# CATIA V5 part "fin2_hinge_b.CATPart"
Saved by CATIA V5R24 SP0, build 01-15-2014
Part number: Hinge B
Bounding box of the stored display mesh (mm): x -3.495 to 3.495, y -3.471 to 3.471, z -5 to 5
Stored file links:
  G:\내 드라이브\04_WORK\00_LECTURE\CAD2020\exam\fin2_hinge_b.CATPart
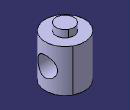
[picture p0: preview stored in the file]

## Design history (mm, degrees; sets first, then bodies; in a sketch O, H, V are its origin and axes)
Body1 (main body)
  Sketch1 on yz-plane, origin (0, 0, 0), H (0, 1, 0), V (0, 0, 1)
    point P1 (0, 5)
    line L1 (0, 5) -> (-1.6, 5)
    line L2 (-1.6, 5) -> (-1.6, 3.75)
    line L3 (-1.6, 3.75) -> (-3.5, 3.75)
    line L4 (-3.5, 3.75) -> (-3.5, -3.75)
    line L5 (-3.5, -3.75) -> (-1.6, -3.75)
    point P6 (-1.6, -3.75)
    line L6 (-1.6, -3.75) -> (-1.6, -5)
    line L7 (-1.6, -5) -> (0, -5)
    point P8 (0, -5)
    axis line L8 (0, 8.3373) -> (0, -8.8361)
    point P9 (0, 8.3373)
    distance L7 L1 = 10
    distance L7 L5 = 1.25
    distance L4 V = 3.5
    distance L6 V = 1.6
    coincidence: P1 V, P6 L2, P9 V, P8 L8
    horizontal: L1 H, L3 H, L5 H, L7 H
    vertical: L2 V, L4 V, L6 V, L8 V
    symmetry: L7 L1 H, L5 L3 H
  Shaft1: profile Sketch1, axis Sketch1.L8, angle 360
  Sketch2 on yz-plane, origin (0, 0.6085, -0.409), H (0, 1, 0), V (0, 0, 1)
    point P1 (-0.6085, 0.409)
    reference intersected line E1 through (0, 0.409) direction (-1, 0) from xy-plane
    reference intersected line E2 through (-0.6085, 0) direction (0, 1) from zx-plane
    coincidence: P1 E1, P1 E2
  Hole1: placed by Sketch2, at (0, 0, 0) direction (-1, 0, 0), diameter 3.5, through (limit type 6)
